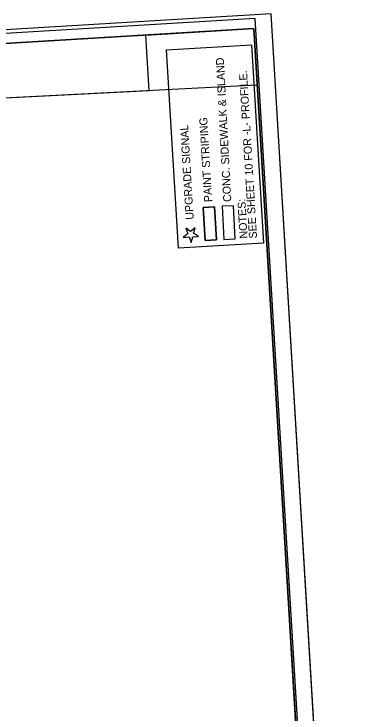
# Model space of a CAD drawing. Extents: x 2368361 to 2369555, y 800599 to 802345.
# Drawn here: x 2369133 to 2369555, y 801472 to 802345 of the extents above; entities that cross this region are included whole.
import ezdxf

# ---------------------------------------------------------------- set-up
doc = ezdxf.new("R2010")
doc.units = 0
for name, color, linetype in [('Default', 7, 'Continuous'), ('Old_Level_1', 7, 'Continuous'), ('Old_Level_10', 7, 'Continuous'), ('Old_Level_11', 7, 'Continuous'), ('Old_Level_15', 7, 'Continuous'), ('Old_Level_2', 7, 'Continuous'), ('Old_Level_4', 7, 'Continuous'), ('Old_Level_5', 7, 'Continuous'), ('Old_Level_6', 7, 'Continuous'), ('Plot Label CELL', 7, 'Continuous'), ('Plot Shape CELL', 7, 'Continuous')]:
    doc.layers.add(name, color=color, linetype=linetype)

msp = doc.modelspace()

# ---------------------------------------------------------------- linework, layer by layer
at = {"layer": 'Default'}
msp.add_line((2368599.6, 802213.8), (2369436.2, 802256.78), dxfattribs=at)
at = {"layer": 'Old_Level_1'}
msp.add_lwpolyline([(2369356.45, 802067.08), (2369363.69, 802067.51), (2369357.58, 802071.41), (2369359.41, 802078.45), (2369353.79, 802073.83), (2369347.67, 802077.74), (2369350.33, 802070.98), (2369344.72, 802066.37), (2369351.97, 802066.8), (2369354.63, 802060.04), (2369356.45, 802067.08)], dxfattribs=at)
at = {"layer": 'Old_Level_10'}
msp.add_lwpolyline([(2368474.82, 800766.64), (2369522.9, 800829.72), (2369432.81, 802327.02), (2368595.82, 802276.66), (2368610.18, 802037.84), (2368399.08, 802025.14)], close=True, dxfattribs=at)
at = {"layer": 'Old_Level_11'}
msp.add_lwpolyline([(2369409.64, 802064.62), (2369407.48, 802105.89), (2369393.23, 802105.15), (2369395.39, 802063.88), (2369409.64, 802064.62)], dxfattribs=at)
at = {"layer": 'Old_Level_15'}
msp.add_line((2369555.37, 800664.89), (2369454.26, 802345.35), dxfattribs=at)
at = {"layer": 'Old_Level_2'}
msp.add_lwpolyline([(2368470.23, 800828.51), (2368399.08, 802025.14), (2368610.18, 802037.84), (2368599.6, 802213.8), (2369302.23, 802249.9), (2369298.05, 802318.92), (2369432.81, 802327.03), (2369518.34, 800891.57)], close=True, dxfattribs=at)
msp.add_lwpolyline([(2368470.23, 800828.51), (2368399.08, 802025.14), (2368610.18, 802037.84), (2368599.6, 802213.8), (2369302.23, 802249.9), (2369298.05, 802318.92), (2369432.81, 802327.03), (2369518.34, 800891.57)], close=True, dxfattribs=at)
at = {"layer": 'Old_Level_4'}
msp.add_lwpolyline([(2369534.62, 800676.67), (2369434.56, 802339.65), (2368381.48, 802276.3), (2368481.53, 800613.31)], close=True, dxfattribs=at)
at = {"layer": 'Old_Level_5'}
for points in [[(2369338.69, 802052.71), (2369323.77, 802300.64), (2369429.79, 802307.01), (2369444.71, 802059.09)], [(2369372.04, 802062.29), (2369369.56, 802103.54), (2369383.8, 802104.4), (2369386.28, 802063.15)]]:
    msp.add_lwpolyline(points, close=True, dxfattribs=at)
for points in [[(2369386.28, 802063.15), (2369383.8, 802104.4), (2369369.56, 802103.54), (2369372.04, 802062.29), (2369386.28, 802063.15)], [(2369409.64, 802064.62), (2369407.48, 802105.89), (2369393.23, 802105.15), (2369395.39, 802063.88), (2369409.64, 802064.62)]]:
    msp.add_lwpolyline(points, dxfattribs=at)
at = {"layer": 'Old_Level_6'}
msp.add_lwpolyline([(2369555.37, 800664.89), (2369454.26, 802345.35), (2368361.24, 802279.59), (2368462.34, 800599.13)], close=True, dxfattribs=at)
at = {"layer": 'Plot Shape CELL'}
for points in [[(2368384.71, 802264), (2368474.79, 800766.67), (2369522.9, 800829.72), (2369432.81, 802327.03)], [(2369522.9, 800829.72), (2368474.82, 800766.64), (2368396.71, 802064.28), (2368546.5, 802073.31), (2368534.5, 802272.98), (2369432.81, 802327.03)]]:
    msp.add_lwpolyline(points, close=True, dxfattribs=at)

# ---------------------------------------------------------------- texts
at = {"layer": 'Plot Label CELL'}
for s, rotation, p in [('CONC. SIDEWALK & ISLAND', 92.998, (2369404.69, 802110.8)), ('SEE SHEET 10 FOR -L- PROFILE.', 93.44297, (2369436.79, 802065.18)), ('PAINT STRIPING', 93.44297, (2369380.89, 802110.62)), ('UPGRADE SIGNAL', 93.44297, (2369357.78, 802088.69)), ('NOTES:', 93.44297, (2369425.1, 802065.14))]:
    msp.add_text(s, height=10, rotation=rotation, dxfattribs=at).set_placement(p)

doc.saveas('drawing.dxf')
